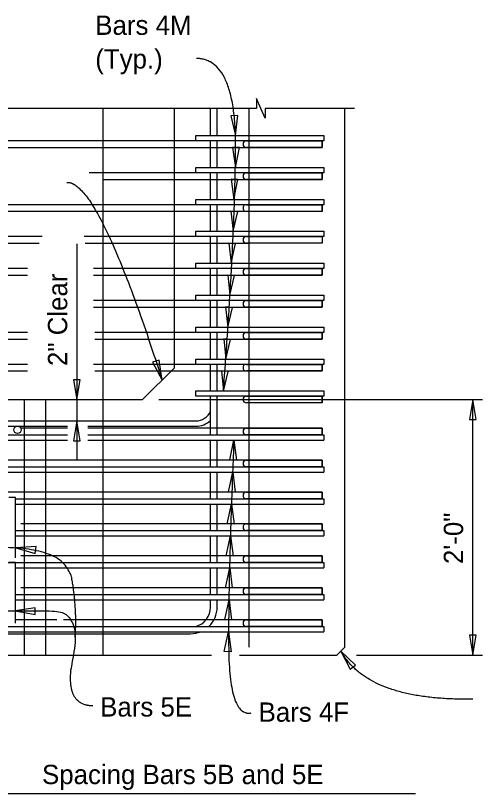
# Model space of a CAD drawing. Extents: x 0.8 to 30.4, y 0.3 to 18.9.
# Drawn here: x 8.77 to 12.42, y 1.9 to 7.99 of the extents above; entities that cross this region are included whole.
import ezdxf

# ---------------------------------------------------------------- set-up
doc = ezdxf.new("R2010")
doc.units = 0
for name, color, linetype in [('BeamConc', 7, 'Continuous'), ('BeamConc_h', 7, 'Continuous'), ('Dimension', 7, 'Continuous'), ('Miscellaneous', 7, 'Continuous'), ('Rebar', 7, 'Continuous'), ('Rebar_h', 7, 'Continuous'), ('TextStructures', 7, 'Continuous')]:
    doc.layers.add(name, color=color, linetype=linetype)

msp = doc.modelspace()

# ---------------------------------------------------------------- linework, layer by layer
at = {"layer": 'BeamConc'}
for p, q in [((10.0157, 5.229), (10.0157, 7.2593)), ((11.3491, 3.0416), (11.3491, 7.2593)), ((9.7657, 4.979), (10.0157, 5.229)), ((8.6897, 4.979), (9.7657, 4.979)), ((11.2866, 2.9791), (11.3491, 3.0416)), ((2.9532, 2.9791), (10.3043, 2.9791)), ((10.5235, 2.9791), (11.2866, 2.9791))]:
    msp.add_line(p, q, dxfattribs=at)
at = {"layer": 'BeamConc_h'}
for p, q in [((9.4532, 7.2593), (9.4532, 2.9791)), ((10.5991, 3.0416), (10.5991, 7.2593))]:
    msp.add_line(p, q, dxfattribs=at)
at = {"layer": 'Dimension'}
for p, q in [((9.2513, 6.198), (9.2513, 4.51)), ((9.3269, 4.979), (9.3269, 4.979)), ((9.8932, 4.979), (12.4247, 4.979)), ((12.3491, 2.9791), (12.3491, 4.979)), ((9.3269, 4.8124), (9.3269, 4.8124)), ((11.4391, 2.9791), (12.4247, 2.9791)), ((5.4532, 1.8952), (11.9002, 1.8952))]:
    msp.add_line(p, q, dxfattribs=at)
for points in [[(9.9401, 7.2592), (7.164, 7.2592), (7.164, 7.1817), (7.1303, 7.2592), (7.0965, 7.3367), (7.0965, 7.2592), (4.2997, 7.2592)], [(11.4247, 7.2592), (10.7254, 7.2592), (10.7254, 7.1817), (10.6916, 7.2592), (10.6579, 7.3367), (10.6579, 7.2592), (9.9401, 7.2592)]]:
    msp.add_lwpolyline(points, dxfattribs=at)
for points in [[(10.4918, 7.0468), (10.5097, 7.2042), (10.4569, 7.2013)], [(10.4914, 6.7968), (10.5225, 6.9521), (10.4696, 6.9537)], [(10.4791, 6.5468), (10.5101, 6.7021), (10.4573, 6.7037)], [(10.4753, 6.2968), (10.5095, 6.4515), (10.4566, 6.4541)], [(10.4592, 6.0468), (10.4934, 6.2015), (10.4405, 6.2041)], [(10.4492, 5.7968), (10.4847, 5.9512), (10.4318, 5.9542)], [(10.4322, 5.5468), (10.4677, 5.7012), (10.4149, 5.7042)], [(10.416, 5.2968), (10.4541, 5.4505), (10.4014, 5.4545)], [(9.9183, 5.1316), (9.8938, 5.2881), (9.8436, 5.2713)], [(10.3976, 5.0463), (10.4357, 5.2), (10.383, 5.204)], [(9.2513, 4.979), (9.278, 5.1346), (9.2247, 5.1346)], [(12.349, 4.979), (12.3224, 4.8233), (12.3757, 4.8233)], [(9.2513, 4.8123), (9.2247, 4.6566), (9.278, 4.6566)], [(10.4804, 4.6613), (10.5002, 4.5041), (10.4473, 4.5064)], [(10.4703, 4.4113), (10.49, 4.2541), (10.4371, 4.2564)], [(10.4613, 4.1613), (10.481, 4.0041), (10.4282, 4.0064)], [(10.4536, 3.9113), (10.4733, 3.7541), (10.4204, 3.7564)], [(8.7732, 3.8175), (8.9259, 3.7752), (8.9313, 3.8279)], [(10.447, 3.6613), (10.4667, 3.5041), (10.4138, 3.5064)], [(10.4416, 3.4113), (10.4614, 3.2541), (10.4085, 3.2564)], [(8.7692, 3.3254), (8.925, 3.2966), (8.9258, 3.3495)], [(10.4376, 3.1613), (10.4573, 3.0041), (10.4045, 3.0064)], [(12.349, 2.979), (12.3757, 3.1347), (12.3224, 3.1347)], [(11.3178, 3.0103), (11.3886, 2.8685), (11.4313, 2.8998)]]:
    msp.add_lwpolyline(points, close=True, dxfattribs=at)
for points in [[(10.3979, 5.0468), (10.4877, 6.2332), (10.4989, 7.6468), (10.1868, 7.6506)], [(9.1721, 6.6799), (9.4188, 6.6949), (9.9183, 5.1316)], [(10.4804, 4.6613), (10.4328, 3.5552), (10.4453, 2.4941), (10.614, 2.5253)], [(9.2374, 3.1183), (9.254, 3.3274), (9.1732, 3.8082), (8.2572, 3.8307), (5.4793, 3.8396)], [(5.4787, 3.3344), (8.8475, 3.3304), (9.2944, 3.3141), (9.1416, 2.5874), (9.376, 2.5826)], [(12.3499, 2.6332), (11.5298, 2.6219), (11.3178, 3.0103)]]:
    msp.add_open_spline(points, degree=2, dxfattribs=at)
at = {"layer": 'Miscellaneous'}
for p, q in [((8.8378, 4.979), (8.8378, 2.9791)), ((9.0045, 4.979), (9.0045, 2.9791))]:
    msp.add_line(p, q, dxfattribs=at)
at = {"layer": 'Rebar'}
for p, q in [((10.297, 7.0468), (10.297, 7.2593)), ((10.3491, 7.0468), (10.3491, 7.2593)), ((10.1824, 7.0468), (11.1824, 7.0468)), ((10.1824, 7.0051), (10.1824, 7.0468)), ((11.1824, 7.0051), (10.1824, 7.0051)), ((10.297, 6.7968), (10.297, 7.0051)), ((10.3491, 6.7968), (10.3491, 7.0051)), ((10.5771, 7.0051), (11.171, 7.0051)), ((11.171, 7.0051), (11.171, 6.953)), ((11.1824, 7.0468), (11.1824, 7.0051)), ((11.171, 6.953), (10.5771, 6.953)), ((10.1824, 6.7968), (11.1824, 6.7968)), ((10.1824, 6.7551), (10.1824, 6.7968)), ((11.1824, 6.7968), (11.1824, 6.7551)), ((11.1824, 6.7551), (10.1824, 6.7551)), ((10.297, 6.5468), (10.297, 6.7551)), ((10.3491, 6.5468), (10.3491, 6.7551)), ((10.5771, 6.7551), (11.171, 6.7551)), ((11.171, 6.703), (10.5771, 6.703)), ((11.171, 6.7551), (11.171, 6.703)), ((10.1824, 6.5468), (11.1824, 6.5468)), ((10.1824, 6.5051), (10.1824, 6.5468)), ((11.1824, 6.5468), (11.1824, 6.5051)), ((11.1824, 6.5051), (10.1824, 6.5051)), ((10.297, 6.2968), (10.297, 6.5051)), ((10.3491, 6.2968), (10.3491, 6.5051)), ((10.5771, 6.5051), (11.171, 6.5051)), ((11.171, 6.5051), (11.171, 6.453)), ((11.171, 6.453), (10.5771, 6.453)), ((10.1824, 6.2968), (11.1824, 6.2968)), ((10.1824, 6.2551), (10.1824, 6.2968)), ((11.1824, 6.2968), (11.1824, 6.2551)), ((11.1824, 6.2551), (10.1824, 6.2551)), ((10.297, 6.0468), (10.297, 6.2551)), ((10.3491, 6.0468), (10.3491, 6.2551)), ((10.5771, 6.2551), (11.171, 6.2551)), ((11.171, 6.2551), (11.171, 6.203)), ((11.171, 6.203), (10.5771, 6.203)), ((10.1824, 6.0468), (11.1824, 6.0468)), ((10.1824, 6.0051), (10.1824, 6.0468)), ((11.1824, 6.0468), (11.1824, 6.0051)), ((11.1824, 6.0051), (10.1824, 6.0051)), ((10.297, 5.7968), (10.297, 6.0051)), ((10.3491, 5.7968), (10.3491, 6.0051)), ((10.5771, 6.0051), (11.171, 6.0051)), ((11.171, 6.0051), (11.171, 5.953)), ((11.171, 5.953), (10.5771, 5.953)), ((10.1824, 5.7968), (11.1824, 5.7968)), ((10.1824, 5.7551), (10.1824, 5.7968)), ((11.1824, 5.7968), (11.1824, 5.7551)), ((11.1824, 5.7551), (10.1824, 5.7551)), ((10.297, 5.5468), (10.297, 5.7551)), ((10.3491, 5.5468), (10.3491, 5.7551)), ((10.5771, 5.7551), (11.171, 5.7551)), ((11.171, 5.7551), (11.171, 5.703)), ((11.171, 5.703), (10.5771, 5.703)), ((10.1824, 5.5468), (11.1824, 5.5468)), ((10.1824, 5.5051), (10.1824, 5.5468)), ((11.1824, 5.5468), (11.1824, 5.5051)), ((11.1824, 5.5051), (10.1824, 5.5051)), ((10.297, 5.2968), (10.297, 5.5051)), ((10.3491, 5.2968), (10.3491, 5.5051)), ((10.5771, 5.5051), (11.171, 5.5051)), ((11.171, 5.5051), (11.171, 5.453)), ((11.171, 5.453), (10.5771, 5.453)), ((10.1824, 5.2968), (11.1824, 5.2968)), ((10.1824, 5.2551), (10.1824, 5.2968)), ((11.1824, 5.2551), (10.1824, 5.2551)), ((10.297, 5.0468), (10.297, 5.2551)), ((10.3491, 5.0468), (10.3491, 5.2551)), ((10.5771, 5.2551), (11.171, 5.2551)), ((11.171, 5.2551), (11.171, 5.203)), ((11.1824, 5.2968), (11.1824, 5.2551)), ((11.171, 5.203), (10.5771, 5.203)), ((10.1824, 5.0468), (11.1824, 5.0468)), ((10.1824, 5.0051), (10.1824, 5.0468)), ((11.1824, 5.0051), (10.1824, 5.0051)), ((10.297, 4.703), (10.297, 5.0051)), ((10.3491, 4.703), (10.3491, 5.0051)), ((10.5771, 5.0051), (11.171, 5.0051)), ((11.171, 5.0051), (11.171, 4.953)), ((11.1824, 5.0468), (11.1824, 5.0051)), ((11.171, 4.953), (10.5771, 4.953)), ((6.8293, 4.8124), (10.1824, 4.8124)), ((6.8293, 4.7707), (9.1776, 4.7707)), ((9.3376, 4.7707), (10.1822, 4.7707)), ((10.5771, 4.7551), (11.171, 4.7551)), ((11.171, 4.7551), (11.171, 4.703)), ((3.0574, 4.703), (9.1776, 4.703)), ((9.3376, 4.703), (11.1824, 4.703)), ((11.171, 4.703), (10.5771, 4.703)), ((11.1824, 4.703), (11.1824, 4.6613)), ((3.0574, 4.6613), (9.1776, 4.6613)), ((9.3376, 4.6613), (11.1824, 4.6613)), ((10.297, 4.453), (10.297, 4.6613)), ((10.3491, 4.453), (10.3491, 4.6613)), ((3.0574, 4.453), (11.1824, 4.453)), ((10.5771, 4.5051), (11.171, 4.5051)), ((11.171, 4.453), (10.5771, 4.453)), ((11.171, 4.5051), (11.171, 4.453)), ((11.1824, 4.453), (11.1824, 4.4113)), ((3.0574, 4.4113), (11.1824, 4.4113)), ((10.297, 4.203), (10.297, 4.4113)), ((10.3491, 4.203), (10.3491, 4.4113)), ((8.7712, 4.213), (8.7192, 4.213)), ((8.7712, 3.739), (8.7712, 4.213)), ((8.7712, 4.203), (11.1824, 4.203)), ((10.5771, 4.2551), (11.171, 4.2551)), ((11.171, 4.203), (10.5771, 4.203)), ((11.171, 4.2551), (11.171, 4.203)), ((11.1824, 4.203), (11.1824, 4.1613)), ((8.7712, 4.1613), (11.1824, 4.1613)), ((10.297, 3.953), (10.297, 4.1613)), ((10.3491, 3.953), (10.3491, 4.1613)), ((10.5771, 4.0051), (11.171, 4.0051)), ((11.171, 4.0051), (11.171, 3.953)), ((8.7712, 3.953), (11.1824, 3.953)), ((8.7712, 3.9113), (11.1824, 3.9113)), ((10.297, 3.703), (10.297, 3.9113)), ((10.3491, 3.703), (10.3491, 3.9113)), ((11.171, 3.953), (10.5771, 3.953)), ((11.1824, 3.953), (11.1824, 3.9113)), ((10.5771, 3.7551), (11.171, 3.7551)), ((11.171, 3.7551), (11.171, 3.703)), ((3.0574, 3.703), (11.1824, 3.703)), ((8.7712, 3.7031), (8.7192, 3.7031)), ((8.7712, 3.2291), (8.7712, 3.7031)), ((8.7712, 3.6613), (11.1824, 3.6613)), ((10.297, 3.453), (10.297, 3.6613)), ((10.3491, 3.453), (10.3491, 3.6613)), ((11.171, 3.703), (10.5771, 3.703)), ((11.1824, 3.703), (11.1824, 3.6613)), ((10.5771, 3.5051), (11.171, 3.5051)), ((11.171, 3.5051), (11.171, 3.453)), ((8.7712, 3.453), (11.1824, 3.453)), ((8.7712, 3.4113), (11.1824, 3.4113)), ((10.297, 3.354), (10.297, 3.4113)), ((10.3491, 3.354), (10.3491, 3.4113)), ((11.171, 3.453), (10.5771, 3.453)), ((11.1824, 3.453), (11.1824, 3.4113)), ((10.5771, 3.2551), (11.171, 3.2551)), ((11.171, 3.2551), (11.171, 3.203)), ((5.0441, 3.203), (11.1824, 3.203)), ((11.171, 3.203), (10.5771, 3.203)), ((11.1824, 3.203), (11.1824, 3.1613)), ((4.099, 3.1457), (10.1408, 3.1457)), ((5.0441, 3.1613), (11.1824, 3.1613))]:
    msp.add_line(p, q, dxfattribs=at)
msp.add_circle((8.7866, 4.742), 0.0287, dxfattribs=at)
for centre, radius, start, end in [((10.5771, 6.9791), 0.026, 90, 270), ((10.5771, 6.7291), 0.026, 90, 270), ((10.5771, 6.4791), 0.026, 90, 270), ((10.5771, 6.2291), 0.026, 90, 270), ((10.5771, 5.9791), 0.026, 90, 270), ((10.5771, 5.7291), 0.026, 90, 270), ((10.5771, 5.4791), 0.026, 90, 270), ((10.5771, 5.2291), 0.026, 90, 270), ((10.5771, 4.9791), 0.026, 90, 270), ((10.1824, 4.9374), 0.125, 270, 336.48194), ((10.1824, 4.9374), 0.1667, 270, 313.43255), ((10.5771, 4.7291), 0.026, 90, 270), ((10.5771, 4.4791), 0.026, 90, 270), ((10.5771, 4.2291), 0.026, 90, 270), ((10.5771, 3.9791), 0.026, 90, 270), ((10.5771, 3.7291), 0.026, 90, 270), ((10.5771, 3.4791), 0.026, 90, 270), ((10.1408, 3.354), 0.1562, 284.80844, 360), ((10.1408, 3.354), 0.2083, 313.53337, 360), ((10.5771, 3.2291), 0.026, 90, 270), ((10.1408, 3.354), 0.2083, 270, 292.32843)]:
    msp.add_arc(centre, radius, start, end, dxfattribs=at)
at = {"layer": 'Rebar_h'}
msp.add_line((11.171, 4.9531), (11.171, 5.0051), dxfattribs=at)
for points in [[(11.171, 7.0051), (3.0688, 7.0051), (3.0688, 6.9531), (11.171, 6.9531)], [(11.171, 6.5051), (3.0688, 6.5051), (3.0688, 6.4531), (11.171, 6.4531)]]:
    msp.add_lwpolyline(points, close=True, dxfattribs=at)
for points in [[(9.4523, 6.7031), (11.171, 6.7031), (11.171, 6.7551), (9.3461, 6.7551)], [(8.9785, 6.2551), (3.0688, 6.2551), (3.0688, 6.2031), (8.9547, 6.2031)], [(10.1824, 6.2551), (9.3089, 6.2551)], [(9.316, 6.2031), (10.5991, 6.2031)], [(8.8656, 6.0051), (6.2013, 6.0051)], [(9.38, 5.9531), (11.171, 5.9531), (11.171, 6.0051), (9.38, 6.0051)], [(6.1913, 5.9531), (8.8656, 5.9531)], [(9.38, 5.7031), (11.171, 5.7031), (11.171, 5.7551), (9.38, 5.7551)], [(8.8656, 5.5051), (3.0688, 5.5051), (3.0688, 5.4531), (8.8656, 5.4531)], [(9.3921, 5.4531), (11.171, 5.4531), (11.171, 5.5051), (9.3921, 5.5051)], [(8.8656, 5.2551), (3.0688, 5.2551), (3.0688, 5.2031), (8.8656, 5.2031)], [(9.3921, 5.2031), (11.171, 5.2031), (11.171, 5.2551), (9.38, 5.2551)], [(9.1776, 4.7551), (8.8105, 4.7551)], [(9.3376, 4.7031), (11.171, 4.7031), (11.171, 4.7551), (9.3376, 4.7551)], [(8.8126, 4.7031), (9.1776, 4.7031)], [(10.1993, 4.5051), (3.0688, 4.5051), (3.0688, 4.4531), (5.4272, 4.4531)], [(8.8126, 4.4531), (11.171, 4.4531), (11.171, 4.5051), (10.1993, 4.5051)], [(10.1993, 4.2551), (3.0688, 4.2551), (3.0688, 4.2031), (5.3858, 4.2031)], [(8.8126, 4.2031), (11.171, 4.2031), (11.171, 4.2551), (10.1993, 4.2551)], [(8.8126, 3.9531), (11.171, 3.9531), (11.171, 4.0051), (8.8126, 4.0051)], [(5.3858, 3.7551), (3.0688, 3.7551), (3.0688, 3.7031), (11.171, 3.7031), (11.171, 3.7551), (8.8126, 3.7551)], [(8.8126, 3.4531), (11.171, 3.4531), (11.171, 3.5051), (8.8126, 3.5051)], [(5.0441, 3.2031), (11.171, 3.2031), (11.171, 3.2551), (9.1459, 3.2551)], [(9.0939, 3.2551), (8.7712, 3.2551)]]:
    msp.add_lwpolyline(points, dxfattribs=at)

# ---------------------------------------------------------------- texts
at = {"layer": 'Dimension'}
for s, p in [('Bars 4M', (9.3952, 7.8348)), ('(Typ.)', (9.3952, 7.5708))]:
    msp.add_text(s, height=0.1512, dxfattribs=at).set_placement(p)
at = {"layer": 'TextStructures'}
for s, p in [('2" Clear', (9.1757, 5.2419)), ('2\'-0"', (12.2734, 3.6915))]:
    msp.add_text(s, height=0.1512, rotation=90, dxfattribs=at).set_placement(p)
for s, p in [('Bars 5E', (9.4334, 2.4973)), ('Bars 4F', (10.6732, 2.4566)), ('Spacing Bars 5B and 5E', (8.9784, 1.9683))]:
    msp.add_text(s, height=0.1512, dxfattribs=at).set_placement(p)

doc.saveas('drawing.dxf')
